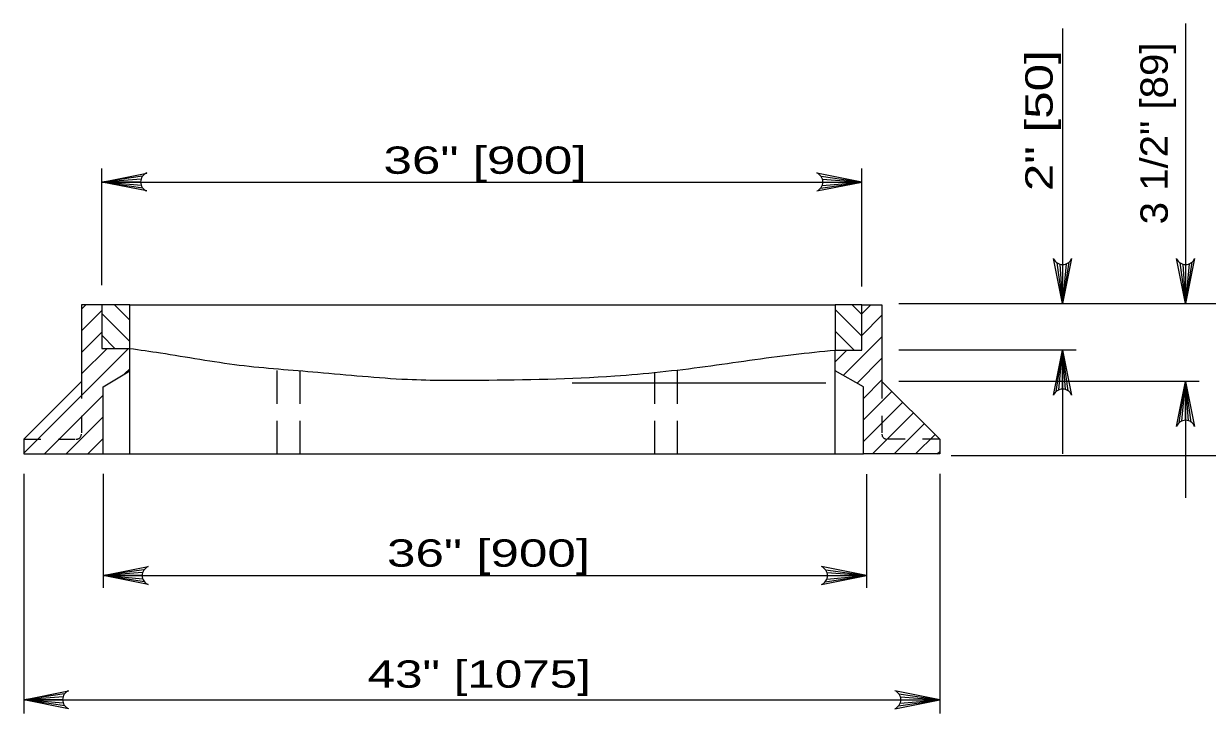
# Model space of a CAD drawing. Extents: x -1431.2 to -1397.2, y -1045.1 to -1001.1.
# Drawn here: x -1409.06 to -1402.18, y -1038.52 to -1034.51 of the extents above; entities that cross this region are included whole.
import ezdxf
from ezdxf.enums import TextEntityAlignment as Align

# ---------------------------------------------------------------- set-up
doc = ezdxf.new("R2010")
doc.units = 0
doc.header["$LTSCALE"] = 0.064
doc.linetypes.add('MEDIUM_DASHED', pattern=[4.5, 3, -1.5])
doc.linetypes.add('SHORT_DASHED', pattern=[2.7, 1.5, -1.2])
doc.layers.add('1', color=7, linetype='Continuous', lineweight=13)

msp = doc.modelspace()

# ---------------------------------------------------------------- linework, layer by layer
at = {"layer": '1'}
for p, q in [((-1403.02292, -1034.54058), (-1403.02292, -1036.13875)), ((-1402.30842, -1034.51175), (-1402.30842, -1036.13875)), ((-1408.60792, -1036.03133), (-1408.60792, -1035.35292)), ((-1404.19033, -1036.03983), (-1404.19033, -1035.35292)), ((-1408.37117, -1035.39917), (-1408.60792, -1035.43233)), ((-1408.37917, -1035.41558), (-1408.60792, -1035.43233)), ((-1408.38158, -1035.43233), (-1408.60792, -1035.43233)), ((-1408.37742, -1035.45358), (-1408.60792, -1035.43233)), ((-1408.36833, -1035.46892), (-1408.60792, -1035.43233)), ((-1408.60792, -1035.43233), (-1404.19033, -1035.43233)), ((-1404.42992, -1035.46892), (-1404.19033, -1035.43233)), ((-1404.42708, -1035.39917), (-1404.19033, -1035.43233)), ((-1404.42083, -1035.45358), (-1404.19033, -1035.43233)), ((-1404.41908, -1035.41558), (-1404.19033, -1035.43233)), ((-1404.41667, -1035.43233), (-1404.19033, -1035.43233)), ((-1403.056, -1035.902), (-1403.02292, -1036.13875)), ((-1403.03958, -1035.91), (-1403.02292, -1036.13875)), ((-1402.98625, -1035.89925), (-1403.02292, -1036.13875)), ((-1403.00158, -1035.90825), (-1403.02292, -1036.13875)), ((-1403.02292, -1035.9125), (-1403.02292, -1036.13875)), ((-1402.34158, -1035.902), (-1402.30842, -1036.13875)), ((-1402.32517, -1035.91), (-1402.30842, -1036.13875)), ((-1402.27183, -1035.89925), (-1402.30842, -1036.13875)), ((-1402.28717, -1035.90825), (-1402.30842, -1036.13875)), ((-1402.30842, -1035.9125), (-1402.30842, -1036.13875)), ((-1403.97425, -1036.13875), (-1401.51458, -1036.13875)), ((-1408.726, -1036.1725), (-1408.70033, -1036.14675)), ((-1408.726, -1036.29783), (-1408.60792, -1036.17975)), ((-1408.44542, -1036.36), (-1408.60792, -1036.19758)), ((-1408.44542, -1036.23475), (-1408.53342, -1036.14675)), ((-1404.19033, -1036.32808), (-1404.34442, -1036.17408)), ((-1404.19033, -1036.20283), (-1404.24642, -1036.14675)), ((-1404.19033, -1036.15525), (-1404.19033, -1036.14675)), ((-1404.19033, -1036.19858), (-1404.1385, -1036.14675)), ((-1404.19033, -1036.15525), (-1404.19033, -1036.14675)), ((-1404.19033, -1036.32383), (-1404.07333, -1036.20683)), ((-1408.726, -1036.42308), (-1408.60792, -1036.305)), ((-1408.5315, -1036.39933), (-1408.60792, -1036.323)), ((-1404.234, -1036.40983), (-1404.34442, -1036.29942)), ((-1404.29792, -1036.55667), (-1404.07333, -1036.33208)), ((-1409.0615, -1037.00908), (-1408.45175, -1036.39933)), ((-1408.726, -1036.54842), (-1408.577, -1036.39933)), ((-1404.34442, -1036.47792), (-1404.27633, -1036.40983)), ((-1402.9435, -1036.40983), (-1403.97425, -1036.40983)), ((-1403.0595, -1036.64933), (-1403.02292, -1036.40983)), ((-1403.04417, -1036.64033), (-1403.02292, -1036.40983)), ((-1403.02292, -1036.63608), (-1403.02292, -1036.40983)), ((-1403.00617, -1036.63858), (-1403.02292, -1036.40983)), ((-1402.98975, -1036.64658), (-1403.02292, -1036.40983)), ((-1403.02292, -1036.40983), (-1403.02292, -1037.013)), ((-1404.21767, -1036.60175), (-1404.07333, -1036.45742)), ((-1408.4755, -1036.54842), (-1408.44542, -1036.5185)), ((-1405.87392, -1036.60008), (-1404.39867, -1036.60008)), ((-1404.18058, -1036.69), (-1404.07333, -1036.58275)), ((-1402.34508, -1036.83083), (-1402.30842, -1036.59133)), ((-1402.32967, -1036.82183), (-1402.30842, -1036.59133)), ((-1402.30842, -1036.81758), (-1402.30842, -1036.59133)), ((-1402.29167, -1036.82008), (-1402.30842, -1036.59133)), ((-1402.27533, -1036.82808), (-1402.30842, -1036.59133)), ((-1402.30842, -1036.59133), (-1402.30842, -1037.26808)), ((-1408.94, -1037.013), (-1408.599, -1036.67208)), ((-1404.18058, -1036.81525), (-1404.015, -1036.64967)), ((-1404.18058, -1036.94058), (-1403.95233, -1036.71242)), ((-1408.81475, -1037.013), (-1408.599, -1036.79733)), ((-1404.12783, -1037.013), (-1403.88983, -1036.77508)), ((-1404.00242, -1037.013), (-1403.82717, -1036.83767)), ((-1408.6895, -1037.013), (-1408.599, -1036.92258)), ((-1403.87717, -1037.013), (-1403.7645, -1036.90042)), ((-1403.75183, -1037.013), (-1403.73733, -1036.9985)), ((-1401.51458, -1037.0245), (-1403.67092, -1037.0245)), ((-1409.0615, -1037.12842), (-1409.0615, -1038.52133)), ((-1408.599, -1037.12842), (-1408.599, -1037.79225)), ((-1404.16333, -1037.131), (-1404.16333, -1037.79225)), ((-1403.73733, -1037.12842), (-1403.73733, -1038.52133)), ((-1408.36225, -1037.68717), (-1408.599, -1037.72025)), ((-1408.37033, -1037.7035), (-1408.599, -1037.72025)), ((-1408.37275, -1037.72025), (-1408.599, -1037.72025)), ((-1408.36858, -1037.7415), (-1408.599, -1037.72025)), ((-1408.3595, -1037.75692), (-1408.599, -1037.72025)), ((-1408.599, -1037.72025), (-1404.16333, -1037.72025)), ((-1404.40292, -1037.75692), (-1404.16333, -1037.72025)), ((-1404.40008, -1037.68717), (-1404.16333, -1037.72025)), ((-1404.39383, -1037.7415), (-1404.16333, -1037.72025)), ((-1404.39208, -1037.7035), (-1404.16333, -1037.72025)), ((-1404.38967, -1037.72025), (-1404.16333, -1037.72025)), ((-1408.82475, -1038.40883), (-1409.0615, -1038.44192)), ((-1403.97408, -1038.40883), (-1403.73733, -1038.44192)), ((-1408.83275, -1038.42517), (-1409.0615, -1038.44192)), ((-1408.83517, -1038.44192), (-1409.0615, -1038.44192)), ((-1408.831, -1038.46317), (-1409.0615, -1038.44192)), ((-1408.82192, -1038.4785), (-1409.0615, -1038.44192)), ((-1409.0615, -1038.44192), (-1403.73733, -1038.44192)), ((-1403.97692, -1038.4785), (-1403.73733, -1038.44192)), ((-1403.96783, -1038.46317), (-1403.73733, -1038.44192)), ((-1403.96608, -1038.42517), (-1403.73733, -1038.44192)), ((-1403.96367, -1038.44192), (-1403.73733, -1038.44192))]:
    msp.add_line(p, q, dxfattribs=at)
at = {"layer": '1', "lineweight": 25}
for p, q in [((-1408.44542, -1036.14675), (-1404.34442, -1036.14675)), ((-1408.44542, -1037.01558), (-1408.44542, -1036.53042)), ((-1404.34442, -1037.01558), (-1404.34442, -1036.53042)), ((-1408.599, -1037.013), (-1404.18058, -1037.013))]:
    msp.add_line(p, q, dxfattribs=at)
at = {"layer": '1', "linetype": 'MEDIUM_DASHED', "lineweight": 25}
for p, q in [((-1407.58858, -1037.013), (-1407.58858, -1036.51875)), ((-1407.45442, -1037.013), (-1407.45442, -1036.52992)), ((-1405.3925, -1037.013), (-1405.3925, -1036.53875)), ((-1405.26075, -1037.013), (-1405.26075, -1036.52442))]:
    msp.add_line(p, q, dxfattribs=at)
at = {"layer": '1', "linetype": 'SHORT_DASHED', "lineweight": 25}
for p, q in [((-1408.726, -1036.59133), (-1408.726, -1036.89808)), ((-1404.07333, -1036.59133), (-1404.07333, -1036.89808)), ((-1409.0615, -1036.92758), (-1408.75558, -1036.92758)), ((-1403.73733, -1036.92758), (-1404.04375, -1036.92758))]:
    msp.add_line(p, q, dxfattribs=at)
at = {"layer": '1'}
for points in [[(-1408.34642, -1035.48458), (-1408.60792, -1035.43233), (-1408.34642, -1035.38)], [(-1404.45183, -1035.48458), (-1404.19033, -1035.43233), (-1404.45183, -1035.38)], [(-1402.97058, -1035.87725), (-1403.02292, -1036.13875), (-1403.07517, -1035.87725)], [(-1402.25617, -1035.87725), (-1402.30842, -1036.13875), (-1402.36075, -1035.87725)], [(-1403.07517, -1036.67133), (-1403.02292, -1036.40983), (-1402.97058, -1036.67133)], [(-1402.22908, -1036.59133), (-1403.53958, -1036.59133), (-1403.97425, -1036.59133)], [(-1402.36075, -1036.85283), (-1402.30842, -1036.59133), (-1402.25617, -1036.85283)], [(-1408.3375, -1037.77258), (-1408.599, -1037.72025), (-1408.3375, -1037.668)], [(-1404.42483, -1037.77258), (-1404.16333, -1037.72025), (-1404.42483, -1037.668)], [(-1408.8, -1038.49425), (-1409.0615, -1038.44192), (-1408.8, -1038.38958)], [(-1403.99883, -1038.49425), (-1403.73733, -1038.44192), (-1403.99883, -1038.38967)]]:
    msp.add_lwpolyline(points, dxfattribs=at)
at = {"layer": '1', "lineweight": 25}
for points in [[(-1408.60792, -1036.14675), (-1408.726, -1036.14675), (-1408.726, -1036.59133), (-1409.0615, -1036.92758), (-1409.0615, -1037.013), (-1408.599, -1037.013), (-1408.599, -1036.62258), (-1408.44542, -1036.53042), (-1408.44542, -1036.39933)], [(-1404.19033, -1036.14675), (-1404.07333, -1036.14675), (-1404.07333, -1036.59133), (-1403.73733, -1036.92758), (-1403.73733, -1037.013), (-1404.18058, -1037.013), (-1404.18058, -1036.62258), (-1404.34442, -1036.53042), (-1404.34442, -1036.40983)], [(-1404.19033, -1036.14675), (-1404.34442, -1036.14675), (-1404.34442, -1036.40983), (-1404.19033, -1036.40983), (-1404.19033, -1036.15525)]]:
    msp.add_lwpolyline(points, dxfattribs=at)
msp.add_lwpolyline([(-1408.44542, -1036.14675), (-1408.60792, -1036.14675), (-1408.60792, -1036.39933), (-1408.44542, -1036.39933)], close=True, dxfattribs=at)
at = {"layer": '1'}
for centre, start, end in [((-1408.32526, -1035.43224), 112.08782, 247.91395), ((-1404.47296, -1035.43224), 292.08605, 67.91218), ((-1403.02294, -1035.85613), 202.08782, 337.91395), ((-1402.30849, -1035.85613), 202.08782, 337.91395), ((-1403.02283, -1036.69246), 22.08782, 157.91395), ((-1402.30838, -1036.87396), 22.08782, 157.91395), ((-1408.3164, -1037.72022), 112.08782, 247.91395), ((-1404.44597, -1037.72022), 292.08605, 67.91218), ((-1408.77886, -1038.44187), 112.08782, 247.91395), ((-1404.01997, -1038.44187), 292.08605, 67.91218)]:
    msp.add_arc(centre, 0.05644, start, end, dxfattribs=at)
at = {"layer": '1', "linetype": 'SHORT_DASHED', "lineweight": 25}
for centre, major_axis, start_param, end_param in [((-1408.75556, -1036.89809), (0.02953, 0), 4.712389, 6.2831853), ((-1404.04377, -1036.89809), (-0.02953, 0), 6.2831853, 7.8539816)]:
    msp.add_ellipse(centre, major_axis=major_axis, ratio=0.999895, start_param=start_param, end_param=end_param, dxfattribs=at)
at = {"layer": '1', "lineweight": 25}
msp.add_spline([(-1408.44542, -1036.39933), (-1408.26667, -1036.42567), (-1407.80825, -1036.49625), (-1407.35242, -1036.53808), (-1406.83067, -1036.57925), (-1406.40633, -1036.58408), (-1405.62583, -1036.55925), (-1405.09967, -1036.50492), (-1404.58633, -1036.43467), (-1404.34442, -1036.40983)], degree=3, dxfattribs=at)

# ---------------------------------------------------------------- texts
at = {"layer": '1', "width": 1.35}
msp.add_text('2" [50]', height=0.1588, rotation=90, dxfattribs=at).set_placement((-1403.08092, -1035.48533))
at = {"layer": '1', "width": 1.1}
msp.add_text('3 1/2" [89]', height=0.1588, rotation=90, dxfattribs=at).set_placement((-1402.41175, -1035.14988), align=Align.CENTER)
at = {"layer": '1'}
for s, width, p in [('36" [900]', 1.4, (-1406.97017, -1035.38467)), ('36" [900]', 1.4, (-1406.94975, -1037.66883)), ('43" [1075]', 1.35, (-1407.06242, -1038.37242))]:
    msp.add_text(s, height=0.1588, dxfattribs=dict(at, width=width)).set_placement(p)

doc.saveas('drawing.dxf')
